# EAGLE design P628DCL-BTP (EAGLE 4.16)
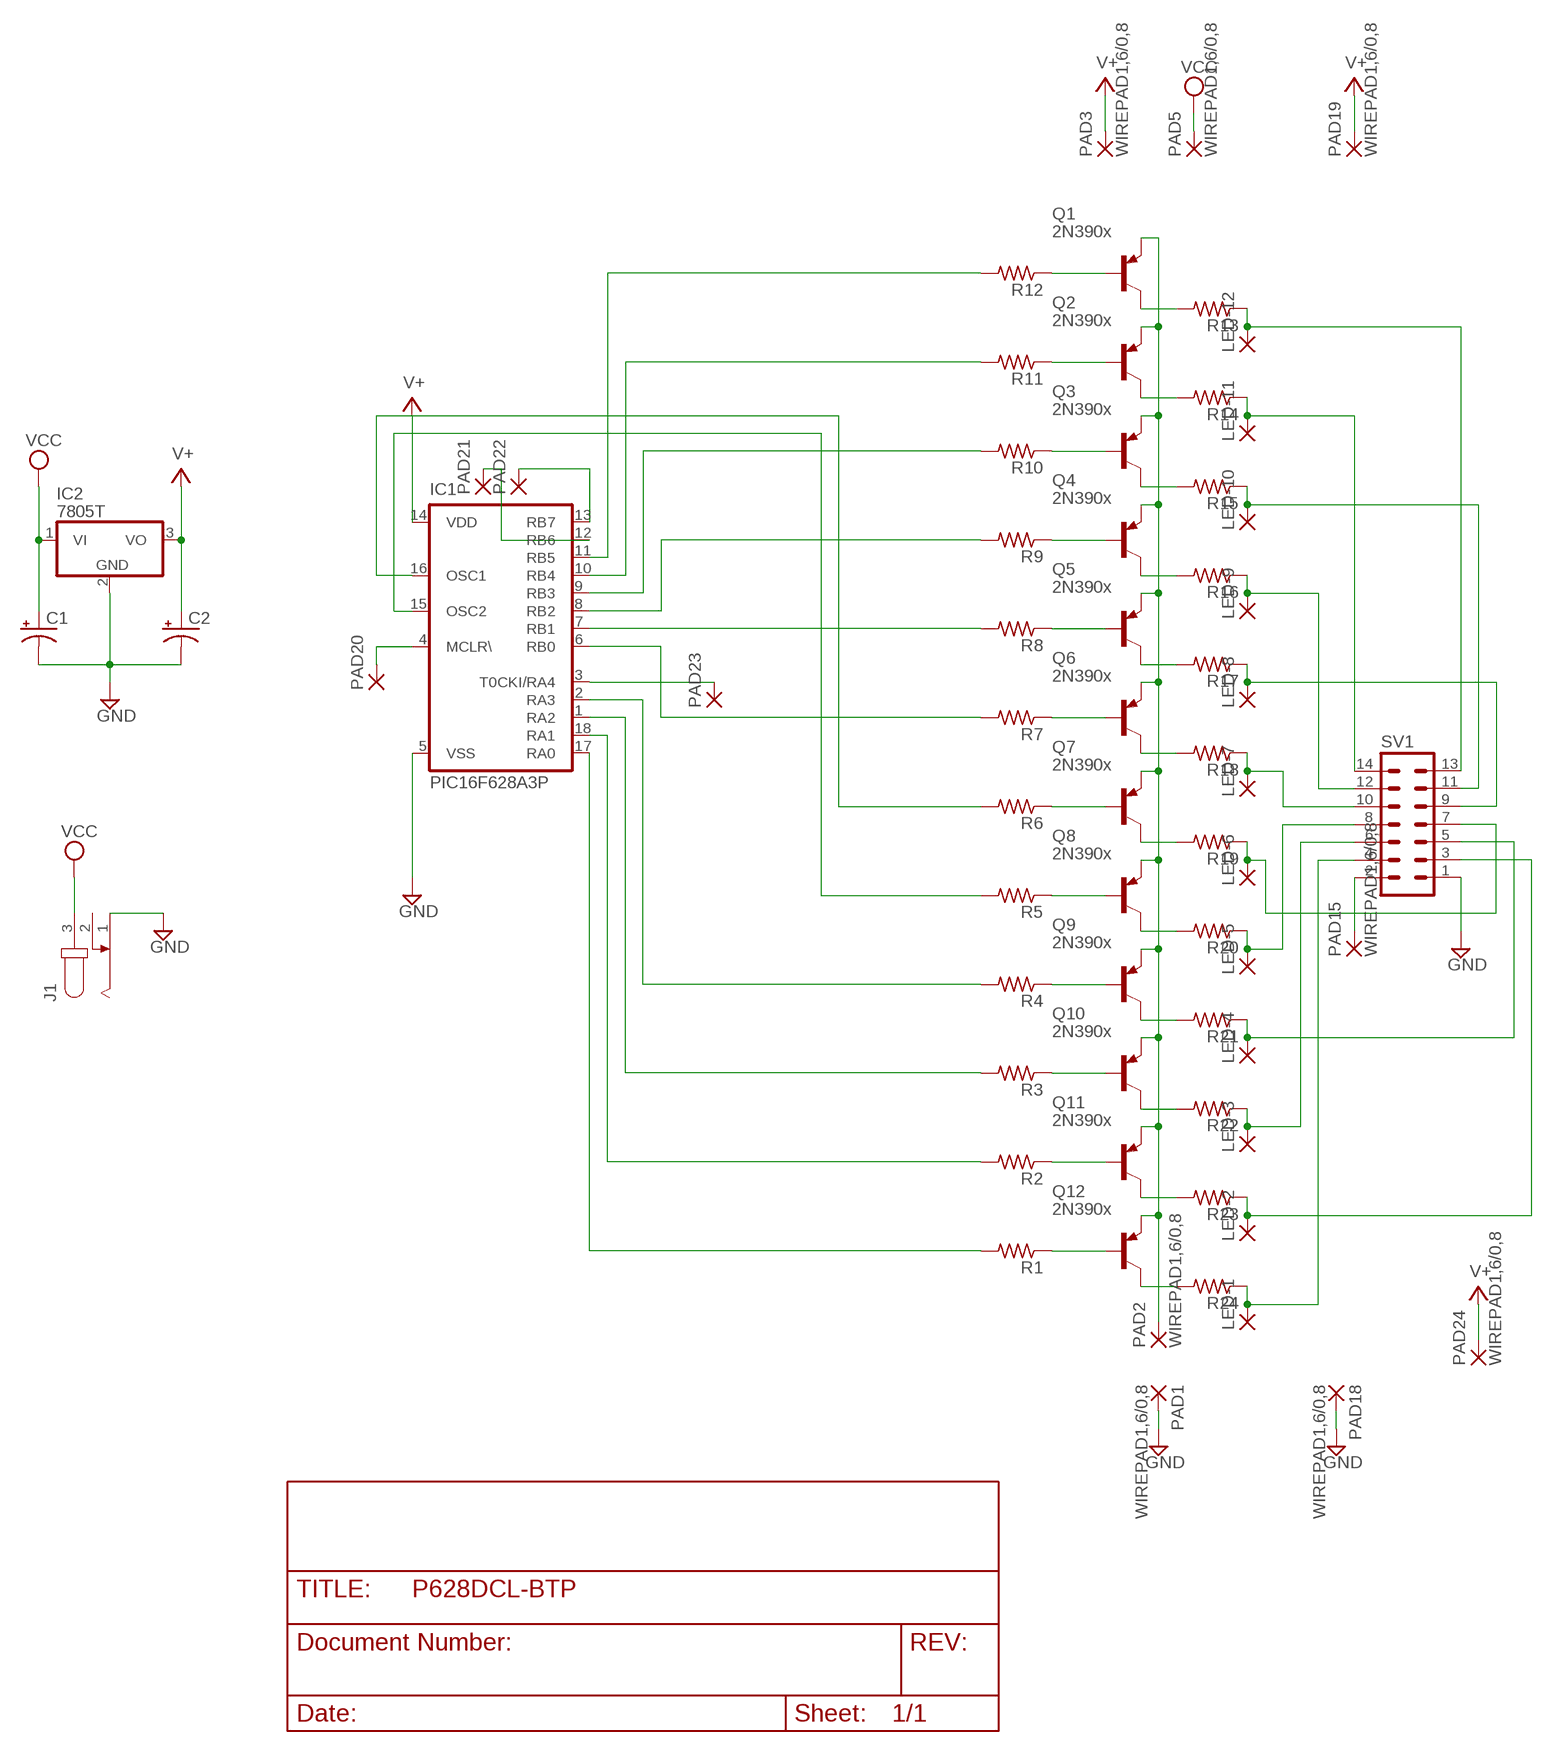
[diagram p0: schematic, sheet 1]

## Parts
C1  CPOL-USE2.5-6  [E2,5-6]
C2  CPOL-USE2.5-6  [E2,5-6]
IC1  PIC16F628A3P  [DIL18]
IC2  7805T  [TO220H]
J1  JACK-PLUG0  [SPC4077]
LED-1  1,6/0,8  [1,6/0,8]
LED-2  1,6/0,8  [1,6/0,8]
LED-3  1,6/0,8  [1,6/0,8]
LED-4  1,6/0,8  [1,6/0,8]
LED-5  1,6/0,8  [1,6/0,8]
LED-6  1,6/0,8  [1,6/0,8]
LED-7  1,6/0,8  [1,6/0,8]
LED-8  1,6/0,8  [1,6/0,8]
LED-9  1,6/0,8  [1,6/0,8]
LED-10  1,6/0,8  [1,6/0,8]
LED-11  1,6/0,8  [1,6/0,8]
LED-12  1,6/0,8  [1,6/0,8]
PAD1  WIREPAD1,6/0,8  [1,6/0,8]
PAD2  WIREPAD1,6/0,8  [1,6/0,8]
PAD3  WIREPAD1,6/0,8  [1,6/0,8]
PAD5  WIREPAD1,6/0,8  [1,6/0,8]
PAD15  WIREPAD1,6/0,8  [1,6/0,8]
PAD18  WIREPAD1,6/0,8  [1,6/0,8]
PAD19  WIREPAD1,6/0,8  [1,6/0,8]
PAD20  1,6/0,8  [1,6/0,8]
PAD21  1,6/0,8  [1,6/0,8]
PAD22  1,6/0,8  [1,6/0,8]
PAD23  1,6/0,8  [1,6/0,8]
PAD24  WIREPAD1,6/0,8  [1,6/0,8]
Q1  2N390x  2N3906  [TO92]
Q2  2N390x  2N3906  [TO92]
Q3  2N390x  2N3906  [TO92]
Q4  2N390x  2N3906  [TO92]
Q5  2N390x  2N3906  [TO92]
Q6  2N390x  2N3906  [TO92]
Q7  2N390x  2N3906  [TO92]
Q8  2N390x  2N3906  [TO92]
Q9  2N390x  2N3906  [TO92]
Q10  2N390x  2N3906  [TO92]
Q11  2N390x  2N3906  [TO92]
Q12  2N390x  2N3906  [TO92]
R1  R-US_0204/7  [0204/7]
R2  R-US_0204/7  [0204/7]
R3  R-US_0204/7  [0204/7]
R4  R-US_0204/7  [0204/7]
R5  R-US_0204/7  [0204/7]
R6  R-US_0204/7  [0204/7]
R7  R-US_0204/7  [0204/7]
R8  R-US_0204/7  [0204/7]
R9  R-US_0204/7  [0204/7]
R10  R-US_0204/7  [0204/7]
R11  R-US_0204/7  [0204/7]
R12  R-US_0204/7  [0204/7]
R13  R-US_0204/7  [0204/7]
R14  R-US_0204/7  [0204/7]
R15  R-US_0204/7  [0204/7]
R16  R-US_0204/7  [0204/7]
R17  R-US_0204/7  [0204/7]
R18  R-US_0204/7  [0204/7]
R19  R-US_0204/7  [0204/7]
R20  R-US_0204/7  [0204/7]
R21  R-US_0204/7  [0204/7]
R22  R-US_0204/7  [0204/7]
R23  R-US_0204/7  [0204/7]
R24  R-US_0204/7  [0204/7]
SV1  MA07-2  [MA07-2]

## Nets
COMMON: PAD2.1(P) Q1.3(E) Q2.3(E) Q3.3(E) Q4.3(E) Q5.3(E) Q6.3(E) Q7.3(E) Q8.3(E) Q9.3(E) Q10.3(E) Q11.3(E) Q12.3(E)
GND: C1.- C2.- IC1.5(VSS) IC2.2(GND) J1.1 PAD1.1(P) PAD18.1(P) SV1.1
N$1: Q1.1(C) R13.2
N$2: Q2.1(C) R14.2
N$3: Q3.1(C) R15.2
N$4: Q4.1(C) R16.2
N$5: Q5.1(C) R17.2
N$6: Q6.1(C) R18.2
N$7: Q7.1(C) R19.2
N$8: Q8.1(C) R20.2
N$9: Q9.1(C) R21.2
N$10: Q10.1(C) R22.2
N$11: Q11.1(C) R23.2
N$12: Q12.1(C) R24.2
N$13: Q12.2(B) R1.1
N$14: Q11.2(B) R2.1
N$15: Q10.2(B) R3.1
N$16: Q9.2(B) R4.1
N$17: LED-10.1(P) R15.1 SV1.11
N$18: IC1.17(RA0) R1.2
N$19: IC1.18(RA1) R2.2
N$20: IC1.1(RA2) R3.2
N$21: IC1.15(OSC2) R5.2
N$22: IC1.2(RA3) R4.2
N$23: IC1.11(RB5) R12.2
N$24: IC1.10(RB4) R11.2
N$25: IC1.9(RB3) R10.2
N$26: IC1.8(RB2) R9.2
N$27: IC1.16(OSC1) R6.2
N$28: IC1.7(RB1) R8.2
N$29: IC1.6(RB0) R7.2
N$30: Q8.2(B) R5.1
N$31: Q7.2(B) R6.1
N$32: Q6.2(B) R7.1
N$33: Q5.2(B) R8.1
N$34: Q4.2(B) R9.1
N$35: Q3.2(B) R10.1
N$36: Q2.2(B) R11.1
N$37: Q1.2(B) R12.1
N$38: LED-1.1(P) R24.1 SV1.4
N$39: LED-2.1(P) R23.1 SV1.3
N$40: LED-3.1(P) R22.1 SV1.6
N$41: LED-4.1(P) R21.1 SV1.5
N$42: LED-5.1(P) R20.1 SV1.8
N$43: LED-6.1(P) R19.1 SV1.7
N$44: LED-7.1(P) R18.1 SV1.10
N$45: LED-8.1(P) R17.1 SV1.9
N$46: LED-9.1(P) R16.1 SV1.12
N$47: PAD15.1(P) SV1.2
N$48: LED-11.1(P) R14.1 SV1.14
N$49: LED-12.1(P) R13.1 SV1.13
N$50: IC1.4(MCLR\) PAD20.1(P)
N$51: IC1.3(T0CKI/RA4) PAD23.1(P)
N$52: IC1.13(RB7) PAD22.1(P)
N$53: IC1.12(RB6) PAD21.1(P)
V+: C2.+ IC1.14(VDD) IC2.3(VO) PAD3.1(P) PAD19.1(P) PAD24.1(P)
VCC: C1.+ IC2.1(VI) J1.3 PAD5.1(P)
Unconnected: J1.2

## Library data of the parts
C1 C2 = rcl:CPOL-US: POLARIZED CAPACITOR, American symbol
IC1 = microchip:PIC16F628A: MICROCONTROLLER 8-Bit PIC16F8X Family - CMOS Flash/EEPROM Pin Compatible : PIC16F83, PIC16CR83, PIC16F84A, PIC16CR84 see also PIC16C*
IC2 = linear:78*: Positive VOLTAGE REGULATOR Source: http://cache.national.com/ds/LM/LM78L05.pdf http://www.fairchildsemi.com/ds/LM/LM7805.pdf
J1 = con-jack:JACK-PLUG: DC POWER JACK Power Jack, DC, Right Angle, Through Hole, Rated 5A at 16VDC, PC Terminals Distributor: Farnell (www.Farnell.de) Drawing: 84N1161.pdf / 84N1162.pdf Manufacturer: SPC Technology (www.spctechnology.com) Type: SPC4077 / SPC 4078
LED-1-LED-12 PAD20-PAD23 = wirepad:1,6/0,8: THROUGH-HOLE PAD
PAD1-PAD3 PAD5 PAD15 PAD18 PAD19 PAD24 = wirepad:WIREPAD: Wire PAD connect wire on PCB
Q1-Q12 = transistor-pnp:2N3906: PNP Transistor
R1-R24 = rcl:R-US_: RESISTOR, American symbol
SV1 = con-lstb:MA07-2: PIN HEADER

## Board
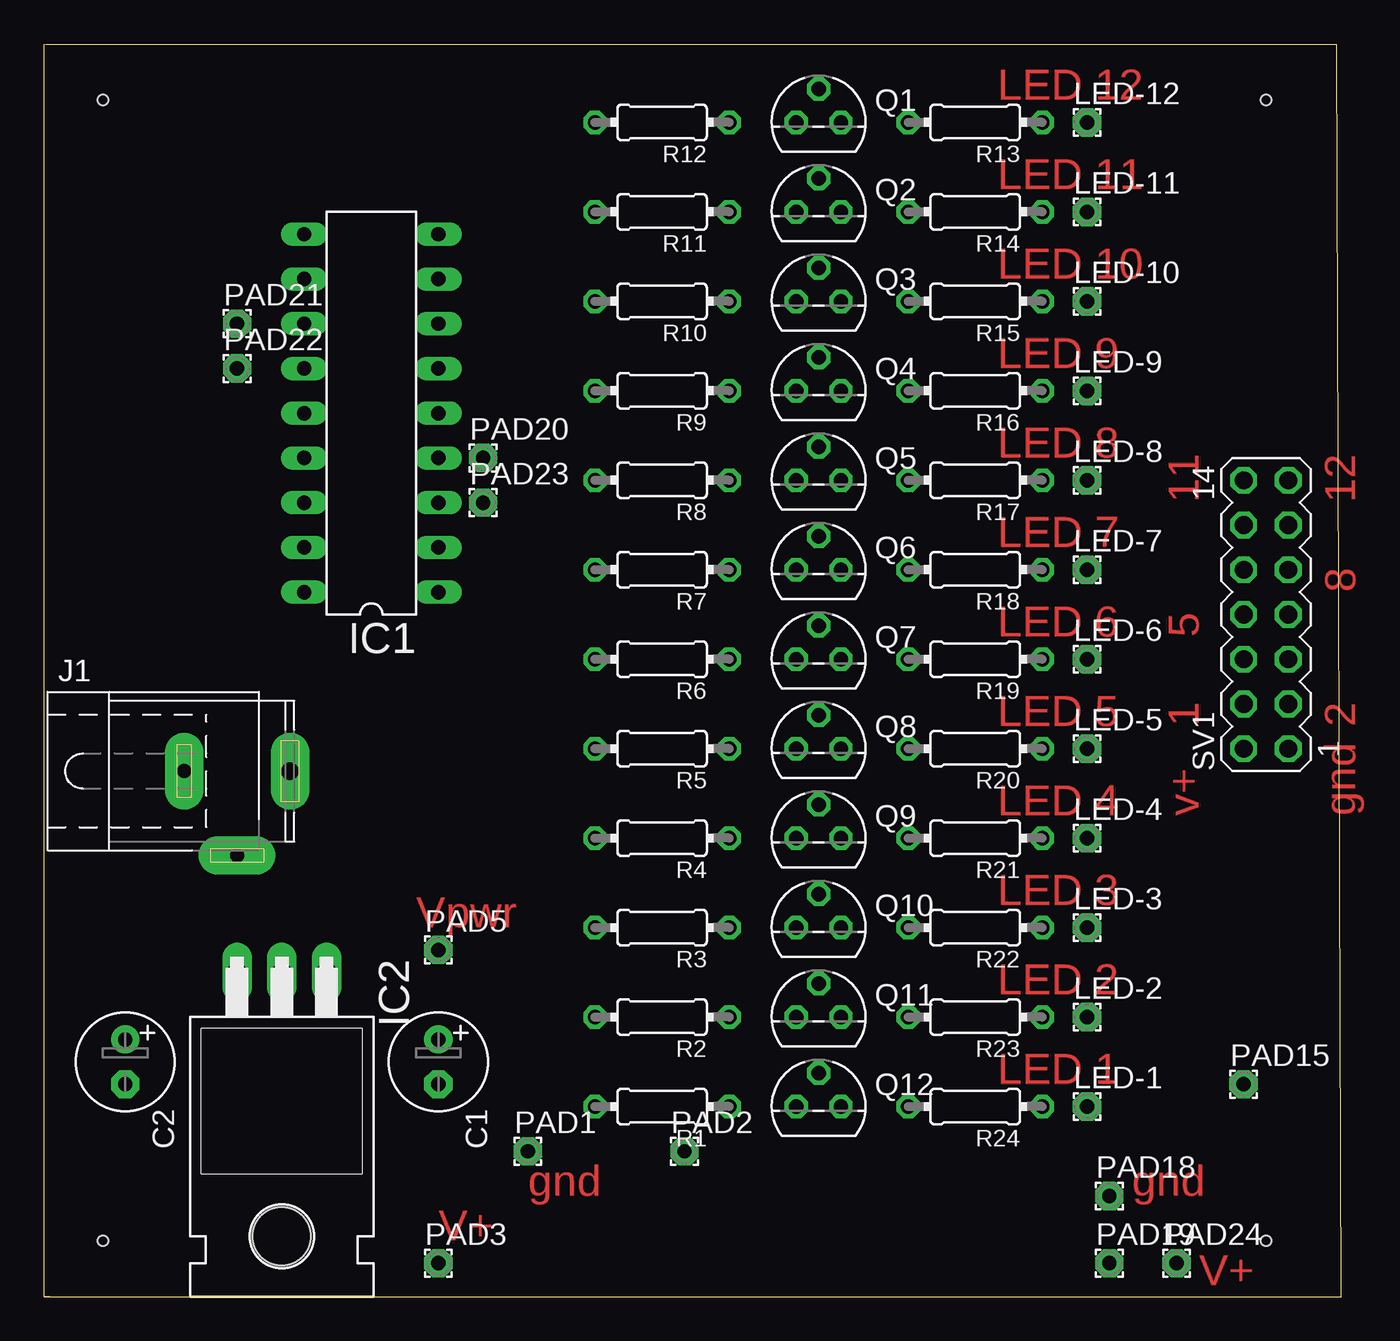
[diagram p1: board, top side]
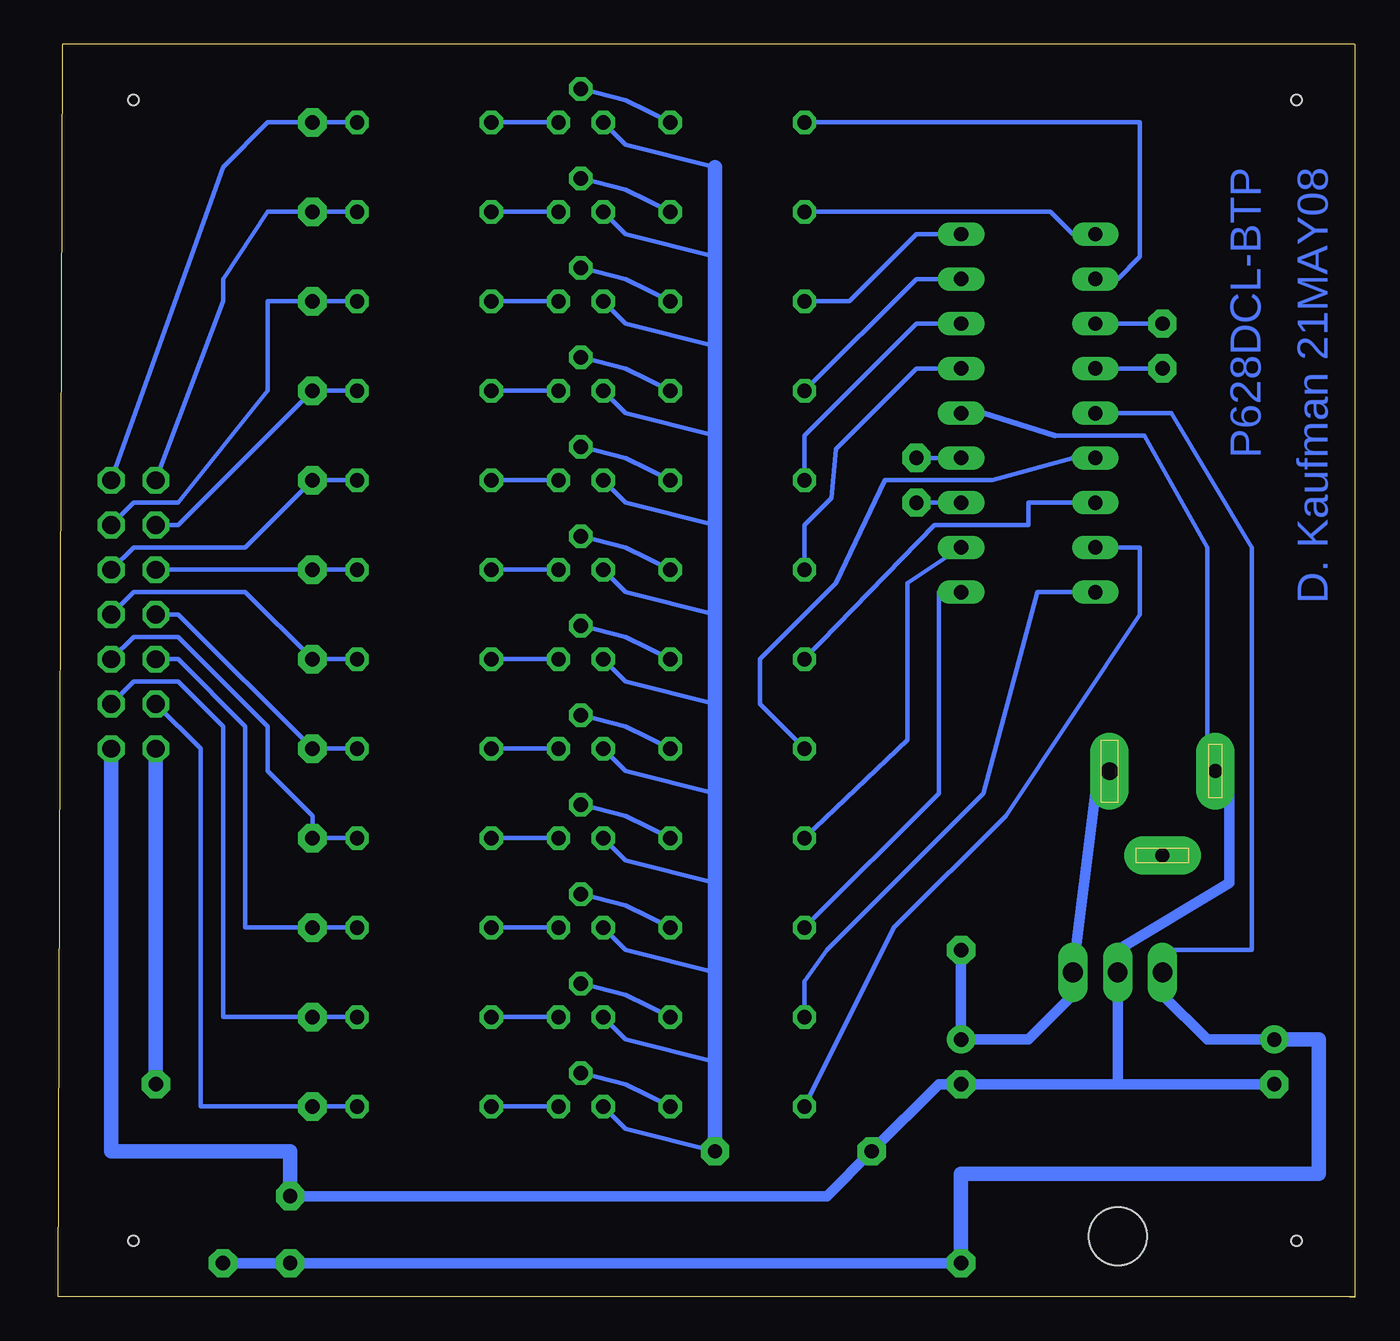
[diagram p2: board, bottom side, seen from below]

Size 73.66 x 71.12 mm. Coordinates in mm from the lower left corner, seen from the top.
Outline: 0.08,71.12 73.41,71.12 73.66,0 0,0
Outline: 0,0 0,71.11
Outline: 0.33,0 0,0
Copper layers (1*16): Top 0.035mm / dielectric 1.5mm / Bottom 0.035mm
Design rules "default": minimum track width 10mil, minimum drill 24mil, track to track 8mil, track to pad 8mil, pad to pad 8mil, via to via 8mil, smd to smd 8mil, copper to edge 40mil, drill to drill 8mil, minimum pad ring 10mil, minimum via ring 8mil, stop-mask expansion 4mil, vias tented up to drill 0mil, thermal gap 10mil
Holes 0.6 mm at 3.34,3.17 69.38,3.17 3.34,67.94 69.38,67.94

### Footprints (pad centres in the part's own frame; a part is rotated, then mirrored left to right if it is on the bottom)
E2,5-6 = drill 0.813 pad 1.6 round: + -1.27,0 | drill 0.813 pad 1.6 octagon: - 1.27,0
DIL18 = drill 0.813 long: 1 -10.16,-3.81; 2 -7.62,-3.81; 3 -5.08,-3.81; 4 -2.54,-3.81; 5 0,-3.81; 6 2.54,-3.81; 7 5.08,-3.81; 8 7.62,-3.81; 9 10.16,-3.81; 10 10.16,3.81; 11 7.62,3.81; 12 5.08,3.81; 13 2.54,3.81; 14 0,3.81; 15 -2.54,3.81; 16 -5.08,3.81; 17 -7.62,3.81; 18 -10.16,3.81
TO220H = drill 1.118 long: 1 -2.54,-10.16; 2 0,-10.16; 3 2.54,-10.16 | hole 3.302: 0,4.826
SPC4077 = drill 0.8 pad 2.184 long: 1 -3,0; 2 0,-4.8 | drill 1 pad 2.184 long: 3 3,0
1,6/0,8 = drill 0.813 pad 1.6 octagon: 1 0,0
TO92 = drill 0.813 octagon: 1 1.27,0; 2 0,1.905; 3 -1.27,0
0204/7 = drill 0.813 octagon: 1 -3.81,0; 2 3.81,0
MA07-2 = drill 1.016 octagon: 1 -7.62,-1.27; 2 -7.62,1.27; 3 -5.08,-1.27; 4 -5.08,1.27; 5 -2.54,-1.27; 6 -2.54,1.27; 7 0,-1.27; 8 0,1.27; 9 2.54,-1.27; 10 2.54,1.27; 11 5.08,-1.27; 12 5.08,1.27; 13 7.62,-1.27; 14 7.62,1.27

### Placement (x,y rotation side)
C1  22.39,13.33 270 top
C2  4.61,13.33 270 top
IC1  18.58,50.16 90 top
IC2  13.5,8.25 180 top
J1  10.96,29.84 0 top
LED-1  59.22,10.79 0 top
LED-2  59.22,15.87 0 top
LED-3  59.22,20.95 0 top
LED-4  59.22,26.03 0 top
LED-5  59.22,31.11 0 top
LED-6  59.22,36.19 0 top
LED-7  59.22,41.27 0 top
LED-8  59.22,46.35 0 top
LED-9  59.22,51.43 0 top
LED-10  59.22,56.51 0 top
LED-11  59.22,61.59 0 top
LED-12  59.22,66.67 0 top
PAD1  27.47,8.25 0 top
PAD2  36.36,8.25 0 top
PAD3  22.39,1.9 0 top
PAD5  22.39,19.68 0 top
PAD15  68.11,12.06 0 top
PAD18  60.49,5.71 0 top
PAD19  60.49,1.9 0 top
PAD20  24.93,47.62 0 top
PAD21  10.96,55.24 0 top
PAD22  10.96,52.7 0 top
PAD23  24.93,45.08 0 top
PAD24  64.3,1.9 0 top
Q1  43.98,66.67 0 top
Q2  43.98,61.59 0 top
Q3  43.98,56.51 0 top
Q4  43.98,51.43 0 top
Q5  43.98,46.35 0 top
Q6  43.98,41.27 0 top
Q7  43.98,36.19 0 top
Q8  43.98,31.11 0 top
Q9  43.98,26.03 0 top
Q10  43.98,20.95 0 top
Q11  43.98,15.87 0 top
Q12  43.98,10.79 0 top
R1  35.09,10.79 180 top
R2  35.09,15.87 180 top
R3  35.09,20.95 180 top
R4  35.09,26.03 180 top
R5  35.09,31.11 180 top
R6  35.09,36.19 180 top
R7  35.09,41.27 180 top
R8  35.09,46.35 180 top
R9  35.09,51.43 180 top
R10  35.09,56.51 180 top
R11  35.09,61.59 180 top
R12  35.09,66.67 180 top
R13  52.87,66.67 180 top
R14  52.87,61.59 180 top
R15  52.87,56.51 180 top
R16  52.87,51.43 180 top
R17  52.87,46.35 180 top
R18  52.87,41.27 180 top
R19  52.87,36.19 180 top
R20  52.87,31.11 180 top
R21  52.87,26.03 180 top
R22  52.87,20.95 180 top
R23  52.87,15.87 180 top
R24  52.87,10.79 180 top
SV1  69.38,38.73 90 top

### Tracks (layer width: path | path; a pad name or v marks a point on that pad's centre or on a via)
COMMON
  Bottom 0.254: Q2.3 41.44,60.32 36.36,59.05 | Q7.3 41.44,34.92 36.36,33.65 | Q12.3 41.44,9.52 PAD2.1 | Q11.3 41.44,14.6 36.36,13.33 | Q10.3 41.44,19.68 36.36,18.41 | Q9.3 41.44,24.76 36.36,23.49 | Q6.3 41.44,40 36.36,38.73 | Q5.3 41.44,45.08 36.36,43.81 | Q4.3 41.44,50.16 36.36,48.89 | Q1.3 41.44,65.4 36.36,64.13 | Q8.3 41.44,29.84 36.36,28.57 | Q3.3 41.44,55.24 36.36,53.97
  Bottom 0.813: PAD2.1 36.36,13.33 36.36,18.41 36.36,23.49 36.36,28.57 36.36,33.65 36.36,38.73 36.36,43.81 36.36,48.89 36.36,53.97 36.36,59.05 36.36,64.13
GND
  Bottom 0.254: 17.06,48.89 11.98,48.89 8.42,42.54 8.42,31.11 J1.1
  Bottom 0.305: 17.06,48.89 21.12,50.16 IC1.5
  Bottom 0.61: 13.5,12.06 C1.- 23.66,12.06 PAD1.1 30.01,5.71 PAD18.1 | C2.- 13.5,12.06 | 13.5,12.06 IC2.2 13.5,19.68 7.15,23.49 7.15,28.57 J1.1
  Bottom 0.813: SV1.1 70.65,8.25 60.49,8.25 PAD18.1
N$1
  Bottom 0.254: Q1.1 R13.2
N$2
  Bottom 0.254: Q2.1 R14.2
N$3
  Bottom 0.254: Q3.1 R15.2
N$4
  Bottom 0.254: Q4.1 R16.2
N$5
  Bottom 0.254: Q5.1 R17.2
N$6
  Bottom 0.254: Q6.1 R18.2
N$7
  Bottom 0.254: Q7.1 R19.2
N$8
  Bottom 0.254: Q8.1 R20.2
N$9
  Bottom 0.254: Q9.1 R21.2
N$10
  Bottom 0.254: Q10.1 R22.2
N$11
  Bottom 0.254: Q11.1 R23.2
N$12
  Bottom 0.254: Q12.1 R24.2
N$13
  Bottom 0.254: R1.1 41.44,12.06 Q12.2
N$14
  Bottom 0.254: R2.1 41.44,17.14 Q11.2
N$15
  Bottom 0.254: R3.1 41.44,22.22 Q10.2
N$16
  Bottom 0.254: R4.1 41.44,27.3 Q9.2
N$17
  Bottom 0.254: R15.1 LED-10.1 61.76,56.51 61.76,51.43 66.84,45.08 69.38,45.08 SV1.11
N$18
  Bottom 0.254: R1.2 26.2,20.95 19.85,27.3 12.23,38.73 12.23,42.54 IC1.17
N$19
  Bottom 0.254: R2.2 31.28,17.9 30.01,19.68 21.12,28.57 18.07,40 IC1.18
N$20
  Bottom 0.254: R3.2 23.66,28.57 23.66,40 IC1.1
N$21
  Bottom 0.254: 16.04,47.62 20.61,46.35 26.71,46.35 29.5,40.51 33.82,36.19 33.82,33.65 R5.2
  Bottom 0.305: IC1.15 16.04,47.62
N$22
  Bottom 0.254: R4.2 25.44,31.62 25.44,40.51 IC1.2
N$23
  Bottom 0.254: R12.2 12.23,66.67 12.23,59.05 13.5,57.78 IC1.11
N$24
  Bottom 0.254: R11.2 17.31,61.59 16.04,60.32 IC1.10
N$25
  Bottom 0.254: R10.2 28.74,56.51 24.93,60.32 IC1.9
N$26
  Bottom 0.254: R9.2 24.93,57.78 IC1.8
N$27
  Bottom 0.254: IC1.16 18.58,45.08 18.58,43.81 23.91,43.81 R6.2
N$28
  Bottom 0.254: R8.2 31.28,48.89 24.93,55.24 IC1.7
N$29
  Bottom 0.254: R7.2 31.28,43.81 29.76,45.33 29.5,48.13 24.93,52.7 IC1.6
N$30
  Bottom 0.254: R5.1 41.44,32.38 Q8.2
N$31
  Bottom 0.254: R6.1 41.44,37.46 Q7.2
N$32
  Bottom 0.254: R7.1 41.44,42.54 Q6.2
N$33
  Bottom 0.254: R8.1 41.44,47.62 Q5.2
N$34
  Bottom 0.254: R9.1 41.44,52.7 Q4.2
N$35
  Bottom 0.254: R10.1 41.44,57.78 Q3.2
N$36
  Bottom 0.254: Q2.2 41.44,62.86 R11.1
N$37
  Bottom 0.254: R12.1 41.44,67.94 Q1.2
N$38
  Bottom 0.254: R24.1 LED-1.1 65.57,10.79 65.57,31.11 SV1.4
N$39
  Bottom 0.254: R23.1 LED-2.1 64.3,15.87 64.3,32.38 66.84,34.92 69.38,34.92 SV1.3
N$40
  Bottom 0.254: R22.1 LED-3.1 63.03,20.95 63.03,32.38 66.84,36.19 SV1.6
N$41
  Bottom 0.254: SV1.5 69.38,37.46 66.84,37.46 61.76,32.38 61.76,29.84 59.22,27.3 LED-4.1 R21.1
N$42
  Bottom 0.254: R20.1 LED-5.1 66.84,38.73 SV1.8
N$43
  Bottom 0.254: R19.1 LED-6.1 63.03,40 69.38,40 SV1.7
N$44
  Bottom 0.254: R18.1 LED-7.1 SV1.10
N$45
  Bottom 0.254: R17.1 LED-8.1 63.03,42.54 69.38,42.54 SV1.9
N$46
  Bottom 0.254: R16.1 LED-9.1 66.84,43.81 SV1.12
N$47
  Bottom 0.813: PAD15.1 SV1.2
N$48
  Bottom 0.254: R14.1 LED-11.1 61.76,61.59 64.3,57.78 64.3,56.51 SV1.14
N$49
  Bottom 0.254: R13.1 LED-12.1 61.76,66.67 64.3,64.13 SV1.13
N$50
  Bottom 0.254: IC1.4 PAD20.1
N$51
  Bottom 0.254: IC1.3 PAD23.1
N$52
  Bottom 0.254: PAD22.1 IC1.13
N$53
  Bottom 0.254: PAD21.1 IC1.12
V+
  Bottom 0.254: IC1.14 10.45,50.16 5.88,42.54 5.88,19.68 10.96,19.68 IC2.3 10.96,17.14
  Bottom 0.61: PAD24.1 PAD19.1 PAD3.1 | 10.96,17.14 8.42,14.6 C2.+
  Bottom 0.813: PAD3.1 22.39,6.98 2.07,6.98 2.07,14.6 C2.+
VCC
  Bottom 0.254: 16.04,17.14 IC2.1
  Bottom 0.61: 16.04,17.14 18.58,14.6 C1.+ PAD5.1 | J1.3 14.77,28.57 IC2.1

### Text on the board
Top: LED 12 | LED 11 | LED 10 | LED 9 | LED 8 | 11 | 12 | LED 7 | 8 | LED 6 | 5 | LED 5 | 1 | 2 | LED 4 | v+ | gnd | LED 3 | Vpwr | LED 2 | LED 1 | gnd | gnd | V+ | V+
Bottom: D. Kaufman 21MAY08 | P628DCL-BTP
